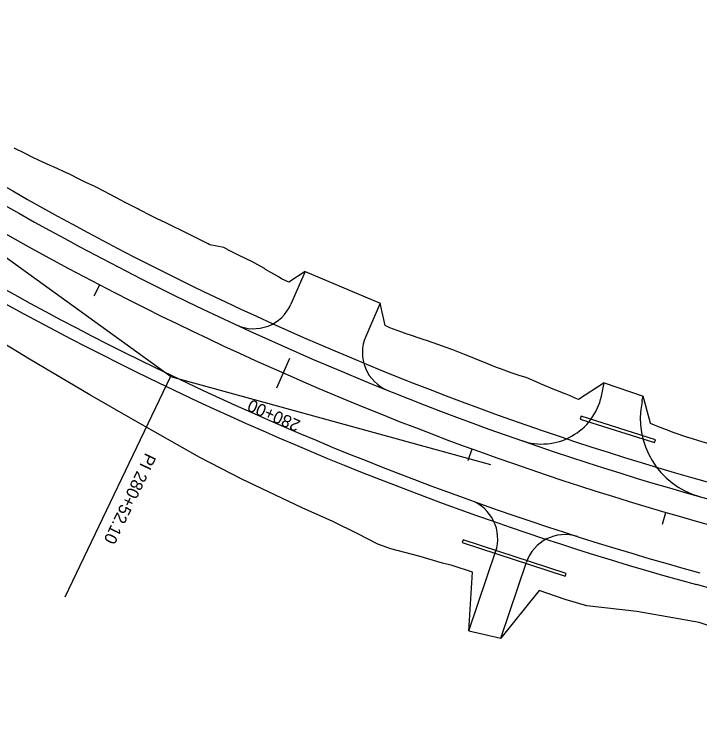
# Model space of a CAD drawing. Extents: x 948761 to 996004, y 1858548 to 1925175.
# Drawn here: x 962744.7 to 963081.2, y 1900955.4 to 1901304.7 of the extents above; entities that cross this region are included whole.
import ezdxf

# ---------------------------------------------------------------- set-up
doc = ezdxf.new("R2010")
doc.units = 0
for name, color, linetype in [('R_Drainage', 7, 'Continuous'), ('R_Horz Alg', 7, 'Continuous'), ('R_Horz Alg Annot', 7, 'Continuous'), ('R_Proposed Const Limits', 7, 'Continuous'), ('R_Proposed Road', 7, 'Continuous')]:
    doc.layers.add(name, color=color, linetype=linetype)

msp = doc.modelspace()

# ---------------------------------------------------------------- linework, layer by layer
at = {"layer": 'R_Drainage'}
for p, q in [((963022.93, 1901107.42), (963022.47, 1901105.99)), ((963022.47, 1901105.99), (963058.94, 1901094.43)), ((963059.39, 1901095.86), (963022.93, 1901107.42)), ((963058.94, 1901094.43), (963059.39, 1901095.86)), ((962965.09, 1901046.73), (962964.62, 1901045.3)), ((963015.58, 1901030.2), (962965.09, 1901046.73)), ((962964.62, 1901045.3), (963015.12, 1901028.78)), ((963015.12, 1901028.78), (963015.58, 1901030.2))]:
    msp.add_line(p, q, dxfattribs=at)
at = {"layer": 'R_Horz Alg'}
msp.add_arc((963492.74, 1902526.81), 1527.89, 234.14059, 254.62332, dxfattribs=at)
at = {"layer": 'R_Horz Alg Annot'}
for q in [(962687.71, 1901223.47), (962978.49, 1901083.63)]:
    msp.add_line((962821.43, 1901126.82), q, dxfattribs=at)
for points in [[(962783.88, 1901166.55), (962786.65, 1901171.87)], [(962873.55, 1901121.27), (962880.01, 1901135.91)], [(962821.43, 1901126.82), (962769.54, 1901018.61)], [(962967.49, 1901085.66), (962969.55, 1901091.3)], [(963062.87, 1901054.39), (963064.55, 1901060.15)]]:
    msp.add_lwpolyline(points, dxfattribs=at)
at = {"layer": 'R_Proposed Const Limits'}
for p, q in [((962967.8, 1901001.98), (962969.58, 1901030.79)), ((963002.34, 1901021.84), (962983.51, 1900998.49))]:
    msp.add_line(p, q, dxfattribs=at)
for points in [[(962840.79, 1901191.58), (962839.89, 1901192.02), (962832.97, 1901195.41), (962832.05, 1901195.87), (962826.08, 1901198.84), (962823.35, 1901200.21), (962819.18, 1901202.24), (962814.61, 1901204.48), (962812.27, 1901205.65), (962805.92, 1901208.85), (962805.4, 1901209.12), (962798.56, 1901212.67), (962797.29, 1901213.33), (962791.74, 1901216.24), (962788.7, 1901217.89), (962784.93, 1901219.83), (962783.64, 1901220.42), (962779.92, 1901222.11), (962777.91, 1901223.04), (962771.21, 1901226.46), (962771.04, 1901226.55), (962764, 1901229.74), (962762.31, 1901230.5), (962756.95, 1901232.93), (962753.45, 1901234.62), (962750, 1901236.32), (962744.71, 1901238.99)], [(962887.46, 1901178.44), (962879.54, 1901173.21), (962875.91, 1901174.86), (962874.69, 1901175.57), (962868.02, 1901179.49), (962867.49, 1901179.83), (962861.31, 1901183.3), (962858.93, 1901184.45), (962854.4, 1901186.68), (962850.23, 1901188.78), (962847.54, 1901190.15), (962840.79, 1901191.58)], [(963034.21, 1901123.81), (963021.68, 1901115.6), (963020.1, 1901116.27), (963017.29, 1901117.48), (963015.61, 1901118.2), (963014.67, 1901118.59), (963014.67, 1901118.59), (963011.06, 1901119.93), (963010.11, 1901120.3), (963003.02, 1901123.35), (963002.08, 1901123.76), (962995.91, 1901126.34), (962993.01, 1901127.26), (962988.56, 1901128.68), (962983.8, 1901130.4), (962981.35, 1901131.36), (962974.76, 1901134.01), (962974.2, 1901134.24), (962967.08, 1901137.17), (962965.77, 1901137.72), (962959.91, 1901139.98), (962956.69, 1901141.19), (962952.67, 1901142.6), (962947.48, 1901144.36), (962945.38, 1901145.08), (962938.26, 1901147.5), (962938.08, 1901147.57), (962930.81, 1901150.15), (962929.09, 1901150.79), (962926.83, 1901151.86), (962924.28, 1901162.82)], [(962969.58, 1901030.79), (962959.73, 1901034.05), (962954.85, 1901035.17), (962943.36, 1901038.71), (962929.58, 1901042.32), (962923.25, 1901044.55), (962913.29, 1901049.69), (962901.13, 1901055.7), (962886.1, 1901062.34), (962856.44, 1901076.5), (962835.87, 1901087.09), (962802.86, 1901105.79), (962781.8, 1901117.87), (962752.22, 1901135.31), (962736.45, 1901144.9)], [(963112.79, 1901084.71), (963103.51, 1901088.68), (963097.7, 1901090.35), (963094, 1901091.42), (963090.28, 1901092.48), (963084.64, 1901094.15), (963082.88, 1901094.67), (963075.49, 1901096.91), (963075.31, 1901096.98), (963068.19, 1901099.45), (963066.1, 1901100.21), (963060.94, 1901102.12), (963057.03, 1901103.88), (963057.01, 1901103.89), (963053.36, 1901117.24)], [(963091.74, 1901002.45), (963080.82, 1901006.15), (963070.8, 1901007.9), (963050.33, 1901011.42), (963025.76, 1901014.3), (963015.15, 1901017.47), (963002.34, 1901021.84)]]:
    msp.add_lwpolyline(points, dxfattribs=at)
at = {"layer": 'R_Proposed Road'}
for p, q in [((962887.46, 1901178.44), (962880.51, 1901162.39)), ((962887.46, 1901178.44), (962924.28, 1901162.82)), ((962924.28, 1901162.82), (962917.22, 1901146.5)), ((962967.8, 1901001.98), (962980.95, 1901040.82)), ((962983.51, 1900998.49), (962996.11, 1901035.68)), ((963331.61, 1900955.4), (963079.64, 1901024.69)), ((962967.8, 1901001.98), (962983.51, 1900998.49))]:
    msp.add_line(p, q, dxfattribs=at)
msp.add_lwpolyline([(963034.21, 1901123.81), (963053.36, 1901117.24)], dxfattribs=at)
for centre, radius, start, end in [((963492.74, 1902526.81), 1507.89, 234.14059, 254.62332), ((963492.74, 1902526.81), 1515.89, 234.14059, 254.62332), ((963492.74, 1902526.81), 1551.89, 234.14059, 254.62332), ((963492.74, 1902526.81), 1557.89, 234.14059, 254.62332), ((962862.16, 1901170.33), 20, 245.0679, 336.6002), ((962935.58, 1901138.56), 20, 156.6002, 248.1325), ((962920.71, 1901142.32), 115, 347.3619, 350.7349), ((963003.65, 1901123.73), 30, 250.7825, 347.3619), ((962920.71, 1901142.32), 135, 348.1472, 349.294), ((963091.98, 1901106.38), 40, 168.1472, 254.2442), ((962962.01, 1901047.23), 20, 341.2877, 70.267), ((963015.05, 1901029.27), 20, 72.3084, 161.2877)]:
    msp.add_arc(centre, radius, start, end, dxfattribs=at)

# ---------------------------------------------------------------- texts
at = {"layer": 'R_Horz Alg Annot'}
for s, rotation, p in [('280+00', 156.2252, (962885.67, 1901105)), ('PI 280+52.10', 244.382, (962809.2, 1901089.75))]:
    msp.add_text(s, height=6, rotation=rotation, dxfattribs=at).set_placement(p)

doc.saveas('drawing.dxf')
